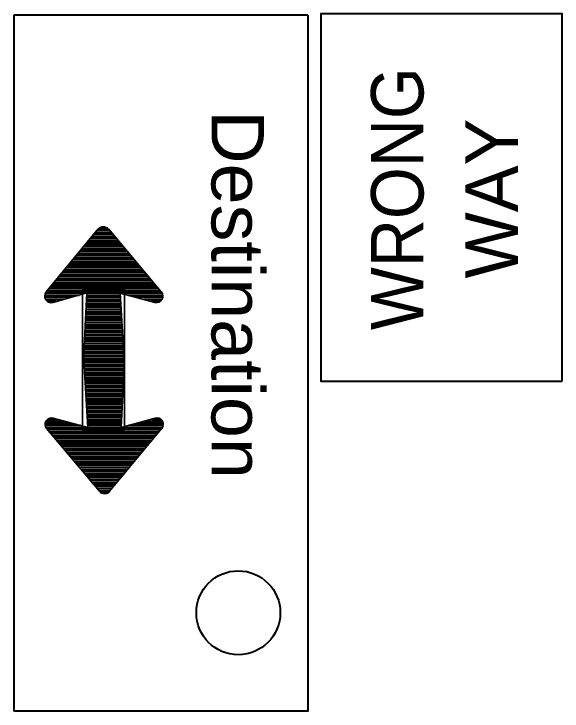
# Model space of a CAD drawing. Extents: x -133 to 547, y -328 to 112.
# Drawn here: x 215.72 to 240.8, y -170.24 to -138.34 of the extents above; entities that cross this region are included whole.
import ezdxf
from ezdxf.enums import TextEntityAlignment as Align

# ---------------------------------------------------------------- set-up
doc = ezdxf.new("R2010")
doc.units = 0
doc.header["$LTSCALE"] = 0.8
doc.layers.add('1', color=7, linetype='Continuous', lineweight=35)

msp = doc.modelspace()

# ---------------------------------------------------------------- linework, layer by layer
at = {"layer": '1', "lineweight": 40}
for p, q in [((229.1575, -138.3992), (215.7175, -138.3992)), ((215.7175, -138.3992), (215.7175, -170.2392)), ((220.0775, -148.2392), (219.5375, -148.2392)), ((219.8575, -148.2392), (219.5375, -148.2392)), ((220.4175, -148.6192), (219.2175, -148.6192)), ((219.8575, -148.6192), (219.2175, -148.6192)), ((220.3175, -148.5192), (219.2975, -148.5192)), ((219.8575, -148.5192), (219.2975, -148.5192)), ((220.2375, -148.4192), (219.3775, -148.4192)), ((219.8575, -148.4192), (219.3775, -148.4192)), ((220.1575, -148.3392), (219.4575, -148.3392)), ((219.8575, -148.3392), (219.4575, -148.3392)), ((220.6375, -148.8992), (218.9775, -148.8992)), ((219.8575, -148.8992), (218.9775, -148.8992)), ((220.5575, -148.8192), (219.0575, -148.8192)), ((219.8575, -148.8192), (219.0575, -148.8192)), ((220.4775, -148.7192), (219.1375, -148.7192)), ((219.8575, -148.7192), (219.1375, -148.7192)), ((220.8775, -149.1992), (218.7575, -149.1992)), ((219.8575, -149.1992), (218.7575, -149.1992)), ((220.7975, -149.0992), (218.8175, -149.0992)), ((219.8575, -149.0992), (218.8175, -149.0992)), ((220.7175, -148.9992), (218.8975, -148.9992)), ((219.8575, -148.9992), (218.8975, -148.9992)), ((221.1975, -149.5792), (218.4375, -149.5792)), ((219.8575, -149.5792), (218.4375, -149.5792)), ((221.1375, -149.4792), (218.5175, -149.4792)), ((219.8575, -149.4792), (218.5175, -149.4792)), ((221.0375, -149.3792), (218.5775, -149.3792)), ((219.8575, -149.3792), (218.5775, -149.3792)), ((220.9575, -149.2992), (218.6575, -149.2992)), ((219.8575, -149.2992), (218.6575, -149.2992)), ((221.4575, -149.8592), (218.1975, -149.8592)), ((219.8575, -149.8592), (218.1975, -149.8592)), ((221.3775, -149.7792), (218.2775, -149.7792)), ((219.8575, -149.7792), (218.2775, -149.7792)), ((221.2975, -149.6792), (218.3375, -149.6792)), ((219.8575, -149.6792), (218.3375, -149.6792)), ((221.6975, -150.1592), (217.9575, -150.1592)), ((219.8575, -150.1592), (217.9575, -150.1592)), ((221.6175, -150.0592), (218.0375, -150.0592)), ((219.8575, -150.0592), (218.0375, -150.0592)), ((221.5375, -149.9592), (218.1175, -149.9592)), ((219.8575, -149.9592), (218.1175, -149.9592)), ((222.0175, -150.5392), (217.6375, -150.5392)), ((219.8575, -150.5392), (217.6375, -150.5392)), ((221.9375, -150.4392), (217.7175, -150.4392)), ((219.8575, -150.4392), (217.7175, -150.4392)), ((221.8575, -150.3392), (217.7975, -150.3392)), ((219.8575, -150.3392), (217.7975, -150.3392)), ((221.7775, -150.2592), (217.8775, -150.2592)), ((219.8575, -150.2592), (217.8775, -150.2592)), ((222.2575, -150.8192), (217.3975, -150.8192)), ((219.8575, -150.8192), (217.3975, -150.8192)), ((222.1775, -150.7392), (217.4775, -150.7392)), ((219.8575, -150.7392), (217.4775, -150.7392)), ((222.0975, -150.6392), (217.5575, -150.6392)), ((219.8575, -150.6392), (217.5575, -150.6392)), ((222.4175, -151.0192), (217.2375, -151.0192)), ((219.8575, -151.0192), (217.2375, -151.0192)), ((222.3575, -150.9192), (217.3175, -150.9192)), ((219.8575, -150.9192), (217.3175, -150.9192)), ((219.8575, -151.1192), (219.0575, -151.1192)), ((218.6975, -151.2192), (217.1375, -151.2192)), ((218.6975, -151.2192), (217.1375, -151.2192)), ((218.3375, -151.2992), (217.1375, -151.2992)), ((218.3375, -151.2992), (217.1375, -151.2992)), ((220.5975, -151.4992), (219.0375, -151.4992)), ((219.8575, -151.4992), (219.0375, -151.4992)), ((220.5775, -151.2192), (219.0575, -151.2192)), ((219.8575, -151.2192), (219.0575, -151.2192)), ((220.5975, -151.2992), (219.0575, -151.2992)), ((219.8575, -151.2992), (219.0575, -151.2992)), ((220.5975, -151.3992), (219.0575, -151.3992)), ((219.8575, -151.3992), (219.0575, -151.3992)), ((222.5375, -151.2192), (220.9375, -151.2192)), ((222.4975, -151.3992), (221.6575, -151.3992)), ((220.6175, -151.5992), (219.0375, -151.5992)), ((219.8575, -151.5992), (219.0375, -151.5992)), ((220.6175, -151.6992), (219.0375, -151.6992)), ((219.8575, -151.6992), (219.0375, -151.6992)), ((220.6175, -151.7792), (219.0375, -151.7792)), ((219.8575, -151.7792), (219.0375, -151.7792)), ((220.6175, -151.8792), (219.0175, -151.8792)), ((219.8575, -151.8792), (219.0175, -151.8792)), ((220.6375, -151.9792), (219.0175, -151.9792)), ((219.8575, -151.9792), (219.0175, -151.9792)), ((220.6375, -152.0792), (219.0175, -152.0792)), ((219.8575, -152.0792), (219.0175, -152.0792)), ((220.6575, -152.4592), (218.9975, -152.4592)), ((219.8575, -152.4592), (218.9975, -152.4592)), ((220.6375, -152.1792), (219.0175, -152.1792)), ((219.8575, -152.1792), (219.0175, -152.1792)), ((220.6375, -152.2592), (219.0175, -152.2592)), ((219.8575, -152.2592), (219.0175, -152.2592)), ((220.6575, -152.3592), (219.0175, -152.3592)), ((219.8575, -152.3592), (219.0175, -152.3592)), ((220.6775, -152.7392), (218.9775, -152.7392)), ((219.8575, -152.7392), (218.9775, -152.7392)), ((220.6575, -152.5592), (218.9975, -152.5592)), ((219.8575, -152.5592), (218.9975, -152.5592)), ((220.6775, -152.6592), (218.9975, -152.6592)), ((219.8575, -152.6592), (218.9975, -152.6592)), ((220.6775, -152.8392), (218.9775, -152.8392)), ((219.8575, -152.8392), (218.9775, -152.8392)), ((220.6775, -152.9392), (218.9775, -152.9392)), ((219.8575, -152.9392), (218.9775, -152.9392)), ((220.6975, -153.0392), (218.9775, -153.0392)), ((219.8575, -153.0392), (218.9775, -153.0392)), ((220.6975, -153.1392), (218.9575, -153.1392)), ((219.8575, -153.1392), (218.9575, -153.1392)), ((220.6975, -153.2192), (218.9575, -153.2192)), ((219.8575, -153.2192), (218.9575, -153.2192)), ((220.6975, -153.3192), (218.9575, -153.3192)), ((219.8575, -153.3192), (218.9575, -153.3192)), ((220.7175, -153.4192), (218.9575, -153.4192)), ((219.8575, -153.4192), (218.9575, -153.4192)), ((220.7175, -153.5192), (218.9375, -153.5192)), ((219.8575, -153.5192), (218.9375, -153.5192)), ((220.7175, -153.6192), (218.9375, -153.6192)), ((219.8575, -153.6192), (218.9375, -153.6192)), ((220.7175, -153.6992), (218.9375, -153.6992)), ((219.8575, -153.6992), (218.9375, -153.6992)), ((220.7375, -153.8992), (218.9175, -153.8992)), ((219.8575, -153.8992), (218.9175, -153.8992)), ((220.7375, -153.9992), (218.9175, -153.9992)), ((219.8575, -153.9992), (218.9175, -153.9992)), ((220.7375, -153.7992), (218.9375, -153.7992)), ((219.8575, -153.7992), (218.9375, -153.7992)), ((220.7575, -154.1792), (218.8975, -154.1792)), ((219.8575, -154.1792), (218.8975, -154.1792)), ((220.7575, -154.0992), (218.9175, -154.0992)), ((219.8575, -154.0992), (218.9175, -154.0992)), ((218.9175, -154.1792), (220.7775, -154.1792)), ((218.9175, -154.2792), (220.7575, -154.2792)), ((218.9375, -154.3792), (220.7575, -154.3792)), ((219.8175, -154.1792), (220.7775, -154.1792)), ((219.8175, -154.2792), (220.7575, -154.2792)), ((219.8175, -154.3792), (220.7575, -154.3792)), ((218.9375, -154.4792), (220.7575, -154.4792)), ((218.9375, -154.5792), (220.7375, -154.5792)), ((218.9575, -154.6592), (220.7375, -154.6592)), ((219.8175, -154.4792), (220.7575, -154.4792)), ((219.8175, -154.5792), (220.7375, -154.5792)), ((219.8175, -154.6592), (220.7375, -154.6592)), ((218.9575, -154.7592), (220.7375, -154.7592)), ((218.9575, -154.8592), (220.7375, -154.8592)), ((218.9575, -154.9592), (220.7175, -154.9592)), ((219.8175, -154.7592), (220.7375, -154.7592)), ((219.8175, -154.8592), (220.7375, -154.8592)), ((219.8175, -154.9592), (220.7175, -154.9592)), ((218.9775, -155.0592), (220.7175, -155.0592)), ((218.9775, -155.1392), (220.7175, -155.1392)), ((218.9775, -155.2392), (220.7175, -155.2392)), ((218.9975, -155.3392), (220.6975, -155.3392)), ((219.8175, -155.0592), (220.7175, -155.0592)), ((219.8175, -155.1392), (220.7175, -155.1392)), ((219.8175, -155.2392), (220.7175, -155.2392)), ((219.8175, -155.3392), (220.6975, -155.3392)), ((218.9975, -155.4392), (220.6975, -155.4392)), ((218.9975, -155.5392), (220.6975, -155.5392)), ((218.9975, -155.6192), (220.6975, -155.6192)), ((219.8175, -155.4392), (220.6975, -155.4392)), ((219.8175, -155.5392), (220.6975, -155.5392)), ((219.8175, -155.6192), (220.6975, -155.6192)), ((218.9975, -155.7192), (220.6775, -155.7192)), ((219.0175, -155.8192), (220.6775, -155.8192)), ((219.0175, -155.9192), (220.6775, -155.9192)), ((219.8175, -155.7192), (220.6775, -155.7192)), ((219.8175, -155.8192), (220.6775, -155.8192)), ((219.8175, -155.9192), (220.6775, -155.9192)), ((219.0175, -156.0192), (220.6775, -156.0192)), ((219.0375, -156.0992), (220.6775, -156.0992)), ((219.0375, -156.1992), (220.6575, -156.1992)), ((219.0375, -156.2992), (220.6575, -156.2992)), ((219.8175, -156.0192), (220.6775, -156.0192)), ((219.8175, -156.0992), (220.6775, -156.0992)), ((219.8175, -156.1992), (220.6575, -156.1992)), ((219.8175, -156.2992), (220.6575, -156.2992)), ((219.0375, -156.3992), (220.6575, -156.3992)), ((219.0575, -156.4992), (220.6575, -156.4992)), ((219.0575, -156.5792), (220.6375, -156.5792)), ((219.8175, -156.3992), (220.6575, -156.3992)), ((219.8175, -156.4992), (220.6575, -156.4992)), ((219.8175, -156.5792), (220.6375, -156.5792)), ((219.0575, -156.6792), (220.6375, -156.6792)), ((219.0575, -156.7792), (220.6375, -156.7792)), ((219.0775, -156.8792), (220.6375, -156.8792)), ((219.8175, -156.6792), (220.6375, -156.6792)), ((219.8175, -156.7792), (220.6375, -156.7792)), ((219.8175, -156.8792), (220.6375, -156.8792)), ((217.1375, -157.1592), (218.7575, -157.1592)), ((217.1775, -156.9792), (218.0375, -156.9792)), ((219.0775, -156.9792), (220.6175, -156.9792)), ((219.0775, -157.0592), (220.6175, -157.0592)), ((219.0975, -157.1592), (220.6175, -157.1592)), ((219.8175, -156.9792), (220.6175, -156.9792)), ((219.8175, -157.0592), (220.6175, -157.0592)), ((219.8175, -157.1592), (220.6175, -157.1592)), ((219.8175, -157.2592), (220.6175, -157.2592)), ((220.9775, -157.1592), (222.5375, -157.1592)), ((220.9775, -157.1592), (222.5375, -157.1592)), ((221.3375, -157.0592), (222.5375, -157.0592)), ((221.3375, -157.0592), (222.5375, -157.0592)), ((217.2575, -157.3592), (222.4375, -157.3592)), ((217.3175, -157.4592), (222.3575, -157.4592)), ((217.4175, -157.5392), (222.2775, -157.5392)), ((219.8175, -157.3592), (222.4375, -157.3592)), ((219.8175, -157.4592), (222.3575, -157.4592)), ((219.8175, -157.5392), (222.2775, -157.5392)), ((217.4975, -157.6392), (222.1975, -157.6392)), ((217.5775, -157.7392), (222.1175, -157.7392)), ((217.6575, -157.8392), (222.0375, -157.8392)), ((219.8175, -157.6392), (222.1975, -157.6392)), ((219.8175, -157.7392), (222.1175, -157.7392)), ((219.8175, -157.8392), (222.0375, -157.8392)), ((217.7375, -157.9392), (221.9575, -157.9392)), ((217.8175, -158.0192), (221.8775, -158.0192)), ((217.8975, -158.1192), (221.7975, -158.1192)), ((217.9775, -158.2192), (221.7175, -158.2192)), ((219.8175, -157.9392), (221.9575, -157.9392)), ((219.8175, -158.0192), (221.8775, -158.0192)), ((219.8175, -158.1192), (221.7975, -158.1192)), ((219.8175, -158.2192), (221.7175, -158.2192)), ((218.0575, -158.3192), (221.6375, -158.3192)), ((218.1375, -158.4192), (221.5575, -158.4192)), ((218.2175, -158.4992), (221.4775, -158.4992)), ((219.8175, -158.3192), (221.6375, -158.3192)), ((219.8175, -158.4192), (221.5575, -158.4192)), ((219.8175, -158.4992), (221.4775, -158.4992)), ((218.2975, -158.5992), (221.3975, -158.5992)), ((218.3775, -158.6992), (221.3375, -158.6992)), ((218.4775, -158.7992), (221.2375, -158.7992)), ((219.8175, -158.5992), (221.3975, -158.5992)), ((219.8175, -158.6992), (221.3375, -158.6992)), ((219.8175, -158.7992), (221.2375, -158.7992)), ((218.5375, -158.8992), (221.1575, -158.8992)), ((218.6375, -158.9792), (221.0975, -158.9792)), ((218.7175, -159.0792), (221.0175, -159.0792)), ((218.7975, -159.1792), (220.9175, -159.1792)), ((219.8175, -158.8992), (221.1575, -158.8992)), ((219.8175, -158.9792), (221.0975, -158.9792)), ((219.8175, -159.0792), (221.0175, -159.0792)), ((219.8175, -159.1792), (220.9175, -159.1792)), ((218.8775, -159.2792), (220.8575, -159.2792)), ((218.9575, -159.3792), (220.7775, -159.3792)), ((219.0375, -159.4592), (220.6975, -159.4592)), ((219.8175, -159.2792), (220.8575, -159.2792)), ((219.8175, -159.3792), (220.7775, -159.3792)), ((219.8175, -159.4592), (220.6975, -159.4592)), ((219.1175, -159.5592), (220.6175, -159.5592)), ((219.1975, -159.6592), (220.5375, -159.6592)), ((219.2575, -159.7592), (220.4575, -159.7592)), ((219.8175, -159.5592), (220.6175, -159.5592)), ((219.8175, -159.6592), (220.5375, -159.6592)), ((219.8175, -159.7592), (220.4575, -159.7592)), ((219.3575, -159.8592), (220.3775, -159.8592)), ((219.4375, -159.9392), (220.2975, -159.9392)), ((219.5175, -160.0392), (220.2175, -160.0392)), ((219.8175, -159.8592), (220.3775, -159.8592)), ((219.8175, -159.9392), (220.2975, -159.9392)), ((219.8175, -160.0392), (220.2175, -160.0392)), ((219.5975, -160.1392), (220.1375, -160.1392)), ((219.8175, -160.1392), (220.1375, -160.1392))]:
    msp.add_line(p, q, dxfattribs=at)
at = {"layer": '1'}
for p, q in [((217.1975, -151.0592), (219.5775, -148.1792)), ((220.0375, -148.1792), (222.4575, -151.0592)), ((219.6375, -160.1792), (217.2175, -157.3192)), ((222.4775, -157.2992), (220.0975, -160.1792))]:
    msp.add_line(p, q, dxfattribs=at)
at = {"layer": '1', "lineweight": 40}
for points in [[(229.1575, -138.3992), (229.1575, -170.2392), (215.7175, -170.2392)], [(219.8575, -148.1392), (219.6375, -148.1392), (219.6375, -148.1392)], [(219.9775, -148.1392), (219.9975, -148.1392), (219.9775, -148.1392), (219.6375, -148.1392), (219.6375, -148.1392)], [(219.0375, -151.1192), (217.1775, -151.1192), (217.1575, -151.1192)], [(219.0375, -151.1192), (217.1775, -151.1192), (217.1575, -151.1192)], [(222.4975, -151.1192), (222.4975, -151.1192), (220.5775, -151.1192), (219.0575, -151.1192)], [(217.9975, -151.3992), (217.1775, -151.3992), (217.1575, -151.3992)], [(217.9975, -151.3992), (217.1775, -151.3992), (217.1575, -151.3992)], [(217.6375, -151.4992), (217.2575, -151.4992), (217.2575, -151.4992)], [(217.6375, -151.4992), (217.2575, -151.4992), (217.2575, -151.4992)], [(222.5375, -151.2992), (222.5175, -151.2992), (221.2975, -151.2992)], [(222.3975, -151.4992), (222.3975, -151.4992), (221.9975, -151.4992)], [(217.2775, -156.8792), (217.2775, -156.8792), (217.6775, -156.8792)], [(222.0375, -156.8792), (222.4175, -156.8792), (222.4175, -156.8792)], [(222.0375, -156.8792), (222.4175, -156.8792), (222.4175, -156.8792)], [(217.1375, -157.0592), (217.1575, -157.0592), (218.3775, -157.0592)], [(217.1775, -157.2592), (217.1775, -157.2592), (219.0975, -157.2592), (220.6175, -157.2592)], [(220.6375, -157.2592), (222.4975, -157.2592), (222.5175, -157.2592)], [(220.6375, -157.2592), (222.4975, -157.2592), (222.5175, -157.2592)], [(221.6775, -156.9792), (222.4975, -156.9792), (222.5175, -156.9792)], [(221.6775, -156.9792), (222.4975, -156.9792), (222.5175, -156.9792)], [(219.6975, -160.2392), (219.6775, -160.2392), (219.6975, -160.2392), (220.0375, -160.2392), (220.0375, -160.2392)], [(219.8175, -160.2392), (220.0375, -160.2392), (220.0375, -160.2392)]]:
    msp.add_lwpolyline(points, dxfattribs=at)
msp.add_lwpolyline([(240.7975, -155.1392), (240.7975, -138.3392), (229.7575, -138.3392), (229.7575, -155.1392)], close=True, dxfattribs=at)
at = {"layer": '1'}
for points in [[(222.1575, -151.5392), (220.5775, -151.1192), (220.7575, -154.1792), (218.8975, -154.1792), (219.0575, -151.0992), (217.4975, -151.5392)], [(217.5175, -156.8392), (219.0975, -157.2592), (218.9175, -154.1792), (220.7775, -154.1792), (220.6175, -157.2592), (222.1775, -156.8392)]]:
    msp.add_lwpolyline(points, dxfattribs=at)
msp.add_lwpolyline([(220.7775, -157.3792), (218.8575, -157.3792), (218.8575, -150.9792), (220.7775, -150.9792)], close=True, dxfattribs=at)
at = {"layer": '1', "lineweight": 40}
msp.add_circle((225.9834, -165.7403), 1.92, dxfattribs=at)
at = {"layer": '1'}
for centre, start, end in [((219.8046, -148.3782), 40.25653, 140.40471), ((217.4246, -151.2541), 140.43005, 285.55122), ((222.2379, -151.2506), 255.11373, 40.25762), ((217.4375, -157.1244), 75.11373, 220.25762), ((222.2509, -157.121), 320.43005, 105.55122), ((219.8709, -159.9969), 220.25653, 320.40471)]:
    msp.add_arc(centre, 0.2976, start, end, dxfattribs=at)

# ---------------------------------------------------------------- texts
for s, rotation, width, p in [('WRONG', 90, 0.95, (234.4575, -146.793)), ('Destination', 270, 1.05, (224.7575, -151.1835))]:
    msp.add_text(s, height=2.4, rotation=rotation, dxfattribs=dict(at, width=width)).set_placement(p, align=Align.CENTER)
msp.add_text('WAY', height=2.4, rotation=90, dxfattribs=at).set_placement((238.7775, -146.7875), align=Align.CENTER)

doc.saveas('drawing.dxf')
